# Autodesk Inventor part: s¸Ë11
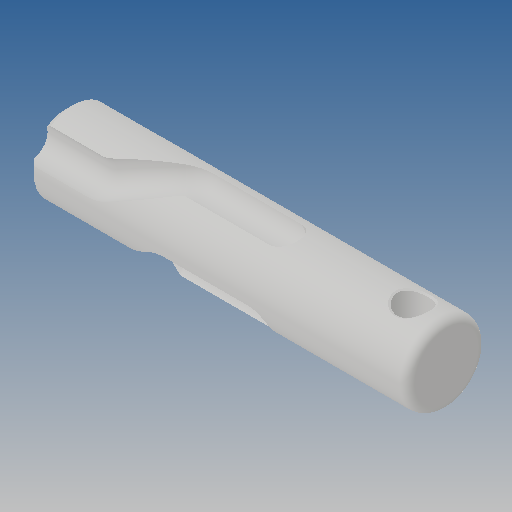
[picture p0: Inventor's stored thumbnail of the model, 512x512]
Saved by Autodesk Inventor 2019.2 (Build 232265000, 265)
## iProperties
Created: 2013-09
Part Number: s¸Ë11
Material: Ogólny
Document SubType Name: Modeling
Designer: CADENGINEERING4
Density: 1 g/cm^3
Appearance: Domyślna
Author: CADENGINEERING4
Revision Number: ÈÎºÎ
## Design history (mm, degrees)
feature "µ¹½Ç2"
node "Bryła1"
